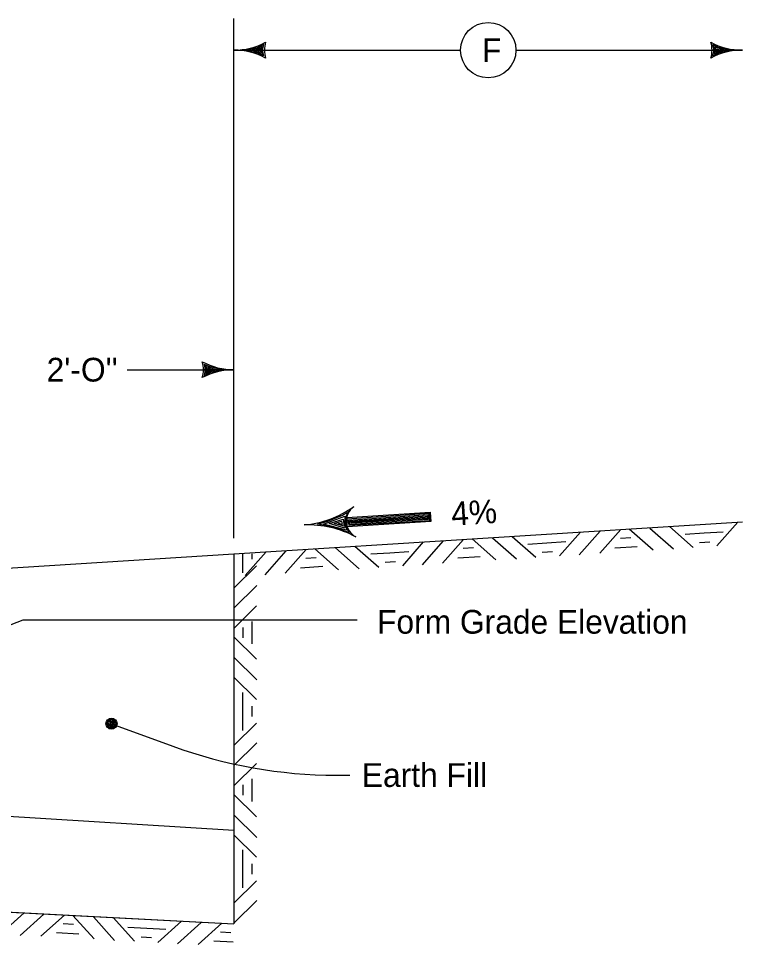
# Model space of a CAD drawing. Extents: x 10133 to 81668, y 2357 to 12713.
# Drawn here: x 11734 to 12191, y 5439 to 6024 of the extents above; entities that cross this region are included whole.
import ezdxf

# ---------------------------------------------------------------- set-up
doc = ezdxf.new("R2010")
doc.units = 0
doc.layers.add('dsnStdNameDate', color=7, linetype='Continuous')
doc.layers.add('SheetAddendum', color=7, linetype='Continuous')

msp = doc.modelspace()

# ---------------------------------------------------------------- linework, layer by layer
at = {"layer": 'dsnStdNameDate'}
for p, q in [((11869.94, 5696.04), (11869.94, 6024.44)), ((11869.94, 6004.44), (12013.1, 6004.44)), ((11869.94, 6004.44), (11889.16, 6004.44)), ((12048.1, 6004.44), (12191.25, 6004.44)), ((12191.25, 6004.44), (12172.03, 6004.44)), ((11802.38, 5802.48), (11869.94, 5802.48)), ((11869.94, 5802.48), (11850.72, 5802.48)), ((11941.21, 5709.26), (11941.21, 5709.26)), ((11941.26, 5706.05), (11994.2, 5709.44)), ((11941.55, 5703.07), (11941.55, 5703.07)), ((11674.79, 5620.34), (11736.68, 5644.41)), ((11736.68, 5644.41), (11947.74, 5644.41)), ((11792.55, 5578.68), (11831.34, 5564.48)), ((11934.51, 5546.18), (11943.11, 5546.18))]:
    msp.add_line(p, q, dxfattribs=at)
for points in [[(11888.77, 6000.88), (11888.04, 6004.46), (11888.8, 6008.06), (11884.5, 6005.99), (11877.68, 6004.46), (11885.01, 6002.74), (11888.17, 6001.33), (11887.38, 6004.46), (11887.68, 6006.77), (11884.86, 6005.42), (11881.07, 6004.46), (11885.1, 6003.28), (11887.2, 6002.56), (11886.81, 6005.63), (11884.02, 6004.46), (11886.21, 6003.76), (11886.24, 6004.82), (11885.22, 6004.49)], [(12172.43, 6008), (12173.15, 6004.42), (12172.4, 6000.82), (12176.69, 6002.89), (12183.52, 6004.42), (12176.18, 6006.14), (12173.03, 6007.55), (12173.81, 6004.42), (12173.51, 6002.11), (12176.33, 6003.46), (12180.12, 6004.42), (12176.09, 6005.6), (12173.99, 6006.32), (12174.38, 6003.25), (12177.18, 6004.42), (12174.98, 6005.11), (12174.95, 6004.06), (12175.97, 6004.39)], [(11851.11, 5806.04), (11851.83, 5802.47), (11851.08, 5798.86), (11855.38, 5800.93), (11862.2, 5802.47), (11854.87, 5804.18), (11851.71, 5805.59), (11852.5, 5802.47), (11852.19, 5800.15), (11855.02, 5801.5), (11858.81, 5802.47), (11854.78, 5803.64), (11852.68, 5804.36), (11853.07, 5801.29), (11855.86, 5802.47), (11853.67, 5803.16), (11853.64, 5802.1), (11854.66, 5802.44)], [(11942.35, 5713.05), (11940.33, 5709.33), (11940.4, 5704.09), (11942.61, 5699.65), (11934.59, 5702.39), (11925.3, 5704.45), (11922.68, 5704.88), (11929.21, 5706.63), (11938.59, 5710.55), (11941.34, 5712.25), (11940.99, 5701.07), (11926.6, 5704.93), (11940.09, 5709.98), (11940.05, 5702.27), (11930.16, 5705.23), (11938.89, 5707.98), (11939.57, 5703.57), (11933.29, 5705.16), (11937.9, 5706.79), (11938.3, 5704.69), (11936.01, 5705.2)], [(11941.17, 5709.06), (11994.01, 5712.43), (11994.39, 5706.44), (11941.55, 5703.07), (11941.4, 5708.2), (11993.37, 5711.72), (11993.54, 5706.95), (11942.67, 5703.9), (11942.31, 5707.46), (11992.69, 5710.88), (11992.76, 5707.7), (11943.29, 5704.54), (11943.01, 5706.78), (11992.14, 5710.18), (11992.19, 5708.39), (11943.9, 5705.37)], [(11792.82, 5581.9), (11791.64, 5581.36), (11789.81, 5580.8), (11789.45, 5578.93), (11789.7, 5577.29), (11790.88, 5575.78), (11792.62, 5575.94), (11794.47, 5576.2), (11795.35, 5577.66), (11795.51, 5579.21), (11794.43, 5581.24), (11793.08, 5581.41), (11791.24, 5580.94), (11789.73, 5579.76), (11789.78, 5578.02), (11790.96, 5576.61), (11792.61, 5576.45), (11794.45, 5576.81), (11794.73, 5577.85), (11795.1, 5579.1), (11794.24, 5580.62), (11792.9, 5580.58), (11791.36, 5580.33), (11790.26, 5579.47), (11790.82, 5577.94), (11791.97, 5577.05), (11793.52, 5576.99), (11793.91, 5577.83), (11794.39, 5578.77), (11793.64, 5579.98), (11792.5, 5580.26), (11791.48, 5579.71), (11791.41, 5578.58), (11791.95, 5577.77), (11792.99, 5577.49), (11793.49, 5577.92), (11793.78, 5578.54), (11793.24, 5579.45), (11792.52, 5579.64), (11791.81, 5579.21), (11791.93, 5578.59), (11792.45, 5578.2), (11793.17, 5578.22), (11793.16, 5578.73), (11792.53, 5579.02)]]:
    msp.add_lwpolyline(points, dxfattribs=at)
for centre, radius in [((12030.6, 6004.44), 17.5), ((11792.55, 5578.68), 3.5)]:
    msp.add_circle(centre, radius, dxfattribs=at)
for centre, radius, start, end in [((11869.94, 6046.94), 42.5, 270, 298.07249), ((11905.57, 6004.44), 16.42, 162.26665, 197.73335), ((12155.62, 6004.44), 16.42, 342.26665, 17.73335), ((12191.25, 6046.94), 42.5, 241.92751, 270), ((11869.94, 5961.94), 42.5, 61.92751, 90), ((12191.25, 5961.94), 42.5, 90, 118.07249), ((11834.3, 5802.48), 16.42, 342.26665, 17.73335), ((11869.94, 5844.98), 42.5, 241.92751, 270), ((11869.94, 5759.98), 42.5, 90, 118.07249), ((11908.36, 5768.53), 64.48, 275.34018, 305.37021), ((11952.22, 5706.75), 11.29, 125.37064, 241.94127), ((11916.58, 5639.9), 64.48, 61.94169, 91.97173), ((11934.51, 5846.18), 300, 249.88442, 270)]:
    msp.add_arc(centre, radius, start, end, dxfattribs=at)
at = {"layer": 'SheetAddendum'}
for p, q in [((12114.32, 5701.46), (12101.1, 5686.46)), ((12119.72, 5701.8), (12134.73, 5688.58)), ((12132.72, 5702.4), (12147.72, 5689.17)), ((12145.13, 5703.41), (12160.13, 5690.18)), ((12188.27, 5706.13), (12175.05, 5691.12)), ((12014.97, 5695.19), (12001.74, 5680.19)), ((12020.37, 5695.53), (12035.37, 5682.31)), ((12033.36, 5696.13), (12048.37, 5682.9)), ((12045.78, 5697.14), (12060.78, 5683.91)), ((12088.91, 5699.86), (12075.69, 5684.85)), ((12101.35, 5700.42), (12088.13, 5685.41)), ((11915.61, 5688.92), (11902.39, 5673.92)), ((11921.01, 5689.26), (11936.02, 5676.04)), ((11934.01, 5689.86), (11949.02, 5676.63)), ((11946.42, 5690.87), (11961.43, 5677.64)), ((11989.56, 5693.59), (11976.34, 5678.58)), ((12002, 5694.15), (11988.78, 5679.14)), ((11869.94, 5686.04), (11869.94, 5452.13)), ((11890.21, 5687.32), (11876.98, 5672.32)), ((11902.64, 5687.88), (11889.42, 5672.87)), ((11869.94, 5664.43), (11884.08, 5678.57)), ((11870.17, 5651.98), (11884.31, 5666.12)), ((11869.94, 5638.97), (11884.08, 5653.11)), ((11869.94, 5633.56), (11884.08, 5619.42)), ((11870.17, 5620.55), (11884.31, 5606.41)), ((11869.94, 5608.1), (11884.08, 5593.96)), ((11869.94, 5564.88), (11884.08, 5579.02)), ((11870.17, 5552.43), (11884.31, 5566.57)), ((11869.94, 5539.42), (11884.08, 5553.56)), ((11869.94, 5534.01), (11884.08, 5519.87)), ((11669.94, 5523.97), (11869.94, 5511.35)), ((11870.17, 5521), (11884.31, 5506.86)), ((11869.94, 5508.55), (11884.08, 5494.41)), ((11869.94, 5465.33), (11884.08, 5479.47)), ((11417.55, 5476.04), (11869.94, 5452.13)), ((11870.17, 5452.88), (11884.31, 5467.02)), ((11737.37, 5459.14), (11722.5, 5445.76)), ((11749.79, 5458.25), (11734.92, 5444.88)), ((11762.79, 5457.79), (11747.92, 5444.42)), ((11768.2, 5457.51), (11781.57, 5442.64)), ((11781.17, 5456.59), (11794.55, 5441.73)), ((11793.62, 5456.16), (11807, 5441.29)), ((11836.78, 5453.88), (11821.91, 5440.51)), ((11849.2, 5453), (11834.33, 5439.62)), ((11862.21, 5452.54), (11847.34, 5439.16))]:
    msp.add_line(p, q, dxfattribs=at)
for points in [[(11869.94, 5686.04), (12191.28, 5706.32)], [(12114.11, 5695.94), (12120.63, 5696.35)], [(12155.04, 5698.55), (12167.04, 5699.3)], [(12167.04, 5699.3), (12179.05, 5700.06)], [(12014.75, 5689.67), (12021.27, 5690.08)], [(12055.68, 5692.28), (12067.69, 5693.03)], [(12067.69, 5693.03), (12079.7, 5693.79)], [(12110.66, 5689.85), (12124.82, 5690.75)], [(12164.15, 5693.31), (12167.41, 5693.52)], [(12167.41, 5693.52), (12170.67, 5693.72)], [(11669.93, 5673.42), (11869.94, 5686.04)], [(11869.94, 5686.04), (11869.94, 5586.49)], [(11875.41, 5686.04), (11875.41, 5674.01)], [(11881.21, 5686.04), (11881.21, 5682.78)], [(11915.4, 5683.4), (11921.92, 5683.81)], [(11956.33, 5686.01), (11968.34, 5686.76)], [(11968.34, 5686.76), (11980.34, 5687.52)], [(12011.3, 5683.58), (12025.46, 5684.48)], [(12064.79, 5687.04), (12068.05, 5687.25)], [(12068.06, 5687.25), (12071.32, 5687.45)], [(11911.95, 5677.32), (11926.11, 5678.21)], [(11965.44, 5680.77), (11968.7, 5680.98)], [(11968.7, 5680.98), (11971.96, 5681.18)], [(11881.29, 5643.36), (11881.29, 5629.17)], [(11875.44, 5639.53), (11875.44, 5633)], [(11875.41, 5598.52), (11875.41, 5586.49)], [(11881.21, 5589.76), (11881.21, 5586.49)], [(11869.94, 5586.49), (11869.94, 5486.94)], [(11875.41, 5586.49), (11875.41, 5574.46)], [(11881.21, 5586.49), (11881.21, 5583.22)], [(11881.29, 5543.81), (11881.29, 5529.62)], [(11875.44, 5539.98), (11875.44, 5533.45)], [(11875.41, 5498.97), (11875.41, 5486.94)], [(11881.21, 5490.2), (11881.21, 5486.94)], [(11869.94, 5486.94), (11869.94, 5452.13)], [(11875.41, 5486.94), (11875.41, 5474.91)], [(11881.21, 5486.94), (11881.21, 5483.67)], [(11417.55, 5476.04), (11869.94, 5452.13)], [(11761.94, 5452.33), (11768.47, 5451.99)], [(11802.9, 5450.19), (11814.91, 5449.56)], [(11814.91, 5449.56), (11826.93, 5448.92)], [(11757.81, 5446.69), (11771.98, 5445.94)], [(11811.35, 5443.94), (11814.61, 5443.76)], [(11814.6, 5443.76), (11817.87, 5443.59)], [(11861.36, 5447.08), (11867.88, 5446.73)], [(11857.22, 5441.43), (11869.34, 5440.79)]]:
    msp.add_lwpolyline(points, dxfattribs=at)

# ---------------------------------------------------------------- texts
at = {"layer": 'dsnStdNameDate'}
for s, p in [('F', (12026.68, 5996.94)), ("2'-O''", (11751.56, 5794.98)), ('Form Grade Elevation', (11960.36, 5635.61)), ('Earth Fill', (11950.75, 5538.75))]:
    msp.add_text(s, height=15, dxfattribs=at).set_placement(p)
msp.add_text('4%', height=15, rotation=3.656, dxfattribs=at).set_placement((12007.64, 5703.82))

doc.saveas('drawing.dxf')
